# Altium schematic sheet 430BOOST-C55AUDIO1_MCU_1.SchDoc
size A4; PageSetup: Record=PageOptions|CenterHorizontal=True|CenterVertical=True|PrintScale=1.00|XCorrection=1.00|YCorrection=1.00|PrintKind=0|BorderSize=5000000|LeftOffset=0|BottomOffset=0|Orientation=2|PaperLength=1000|PaperWidth=1000|Scale=100|PaperSource=7|PrintQuality=-4|MediaType=1|DitherType=10|PaperKind=A4|PrintScaleMode=1
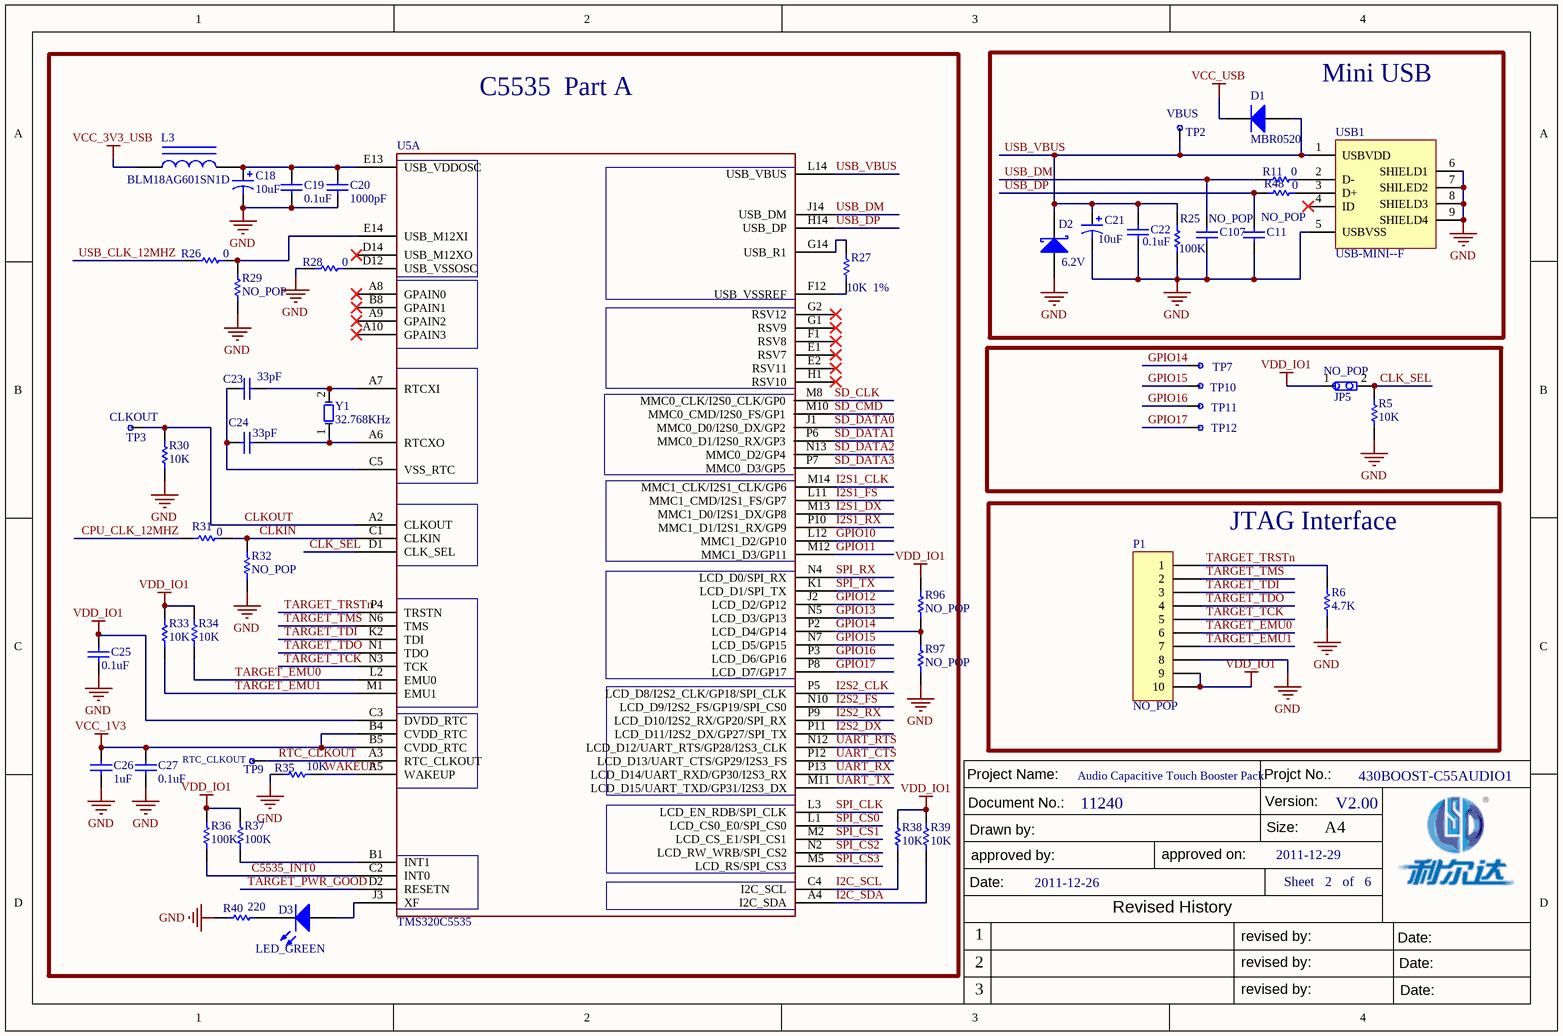
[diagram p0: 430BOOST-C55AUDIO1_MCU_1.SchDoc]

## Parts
C11  NO_POP  [0402-C]
C18  10uF  [0805-C]
C19  0.1uF  [0402-C]
C20  1000pF  [0402-C]
C21  10uF  [0805-C]
C22  0.1uF  [0402-C]
C23  33pF  [0402-C]
C24  33pF  [0402-C]
C25  0.1uF  [0402-C]
C26  1uF  [0603-C]
C27  0.1uF  [0402-C]
C107  NO_POP  [0402-C]
D1  MBR0520  [SOD-123-1]
D2  6.2V  [SOD-123-1]
D3  LED_GREEN  [0603-1]
JP5  NO_POP  [SIP2-2.54]
L3  BLM18AG601SN1D  [0603-L]
P1  NO_POP  [SIP10-2.0]
R5  10K  [0402-R]
R6  4.7K  [0402-R]
R11  0  [0402-R]
R25  100K  [0402-R]
R26  0  [0402-R]
R27  10K  1%  [0402-R]
R28  0  [0402-R]
R29  NO_POP  [0402-R]
R30  10K  [0402-R]
R31  0  [0402-R]
R32  NO_POP  [0402-R]
R33  10K  [0402-R]
R34  10K  [0402-R]
R35  10K  [0402-R]
R36  100K  [0402-R]
R37  100K  [0402-R]
R38  10K  [0402-R]
R39  10K  [0402-R]
R40  220  [0402-R]
R48  0  [0402-R]
R96  NO_POP  [0402-R]
R97  NO_POP  [0402-R]
TP2  VBUS  [SIP1-TEST]
TP3  CLKOUT  [SIP1-TEST]
TP7  TextPoint  [SIP1-TEST]  (value not drawn)
TP9  RTC_CLKOUT  [SIP1-TEST]
TP10  TextPoint  [SIP1-TEST]  (value not drawn)
TP11  TextPoint  [SIP1-TEST]  (value not drawn)
TP12  TextPoint  [SIP1-TEST]  (value not drawn)
U5  TMS320C5535  [BGA-N144-0.8MM]  (part A of 2)
USB1  USB-MINI--F  [USB-MIN-F]
Y1  32.768KHz  [SMD4015-2]

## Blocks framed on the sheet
C5535  Part A: C18-C20 C23-C27 D3 L3 R26-R40 R96 R97 TP3 TP9 U5 Y1
Mini USB: C11 C21 C22 C107 D1 D2 R11 R25 R48 TP2 USB1
JTAG Interface: P1 R6

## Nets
GND: C11.2 C18.2 C19.1 C20.1 C21.2 C22.2 C25.1 C26.1 C27.1 C107.2 D2.1(A) P1.8 R5.1 R6.1 R25.1 R28.1 R29.1 R30.1 R32.1 R35.1 R40.1 R97.2 USB1.5(USBVSS) USB1.6(SHIELD1) USB1.7(SHILED2) USB1.8(SHIELD3) USB1.9(SHIELD4)
VCC_1V3: C26.2 C27.2 U5.B4(CVDD_RTC) U5.B5(CVDD_RTC)
VCC_3V3_USB: L3.1
VCC_USB: D1.2(K)
VDD_IO1: C25.2 JP5.1 P1.9 P1.10 R33.2 R34.2 R36.2 R37.2 R38.2 R39.2 R96.2 U5.C3(DVDD_RTC)
C5535_INT0: R36.1 U5.C2(INT0)
CLK_SEL: JP5.2 R5.2 U5.D1(CLK_SEL)
CLKIN: R31.1 R32.2 U5.C1(CLKIN)
CLKOUT: R30.2 TP3.1 U5.A2(CLKOUT)
CPU_CLK_12MHZ: R31.2
GPIO10: U5.L12(MMC1_D2/GP10)
GPIO11: U5.M12(MMC1_D3/GP11)
GPIO12: U5.J2(LCD_D2/GP12)
GPIO13: U5.N5(LCD_D3/GP13)
GPIO14: R96.1 R97.1 TP7.1 U5.P2(LCD_D4/GP14)
GPIO15: TP10.1 U5.N7(LCD_D5/GP15)
GPIO16: TP11.1 U5.P3(LCD_D6/GP16)
GPIO17: TP12.1 U5.P8(LCD_D7/GP17)
I2C_SCL: R38.1 U5.C4(I2C_SCL)
I2C_SDA: R39.1 U5.A4(I2C_SDA)
I2S1_CLK: U5.M14(MMC1_CLK/I2S1_CLK/GP6)
I2S1_DX: U5.M13(MMC1_D0/I2S1_DX/GP8)
I2S1_FS: U5.L11(MMC1_CMD/I2S1_FS/GP7)
I2S1_RX: U5.P10(MMC1_D1/I2S1_RX/GP9)
I2S2_CLK: U5.P5(LCD_D8/I2S2_CLK/GP18/SPI_CLK)
I2S2_DX: U5.P11(LCD_D11/I2S2_DX/GP27/SPI_TX)
I2S2_FS: U5.N10(LCD_D9/I2S2_FS/GP19/SPI_CS0)
I2S2_RX: U5.P9(LCD_D10/I2S2_RX/GP20/SPI_RX)
RTC_CLKOUT: TP9.1 U5.A3(RTC_CLKOUT)
SD_CLK: U5.M8(MMC0_CLK/I2S0_CLK/GP0)
SD_CMD: U5.M10(MMC0_CMD/I2S0_FS/GP1)
SD_DATA0: U5.J1(MMC0_D0/I2S0_DX/GP2)
SD_DATA1: U5.P6(MMC0_D1/I2S0_RX/GP3)
SD_DATA2: U5.N13(MMC0_D2/GP4)
SD_DATA3: U5.P7(MMC0_D3/GP5)
SPI_CLK: U5.L3(LCD_EN_RDB/SPI_CLK)
SPI_CS0: U5.L1(LCD_CS0_E0/SPI_CS0)
SPI_CS1: U5.M2(LCD_CS_E1/SPI_CS1)
SPI_CS2: U5.N2(LCD_RW_WRB/SPI_CS2)
SPI_CS3: U5.M5(LCD_RS/SPI_CS3)
SPI_RX: U5.N4(LCD_D0/SPI_RX)
SPI_TX: U5.K1(LCD_D1/SPI_TX)
TARGET_EMU0: P1.6 R34.1 U5.L2(EMU0)
TARGET_EMU1: P1.7 R33.1 U5.M1(EMU1)
TARGET_PWR_GOOD: U5.D2(RESETN)
TARGET_TCK: P1.5 U5.N3(TCK)
TARGET_TDI: P1.3 U5.K2(TDI)
TARGET_TDO: P1.4 U5.N1(TDO)
TARGET_TMS: P1.2 U5.N6(TMS)
TARGET_TRSTn: P1.1 R6.2 U5.P4(TRSTN)
UART_CTS: U5.P12(LCD_D13/UART_CTS/GP29/I2S3_FS)
UART_RTS: U5.N12(LCD_D12/UART_RTS/GP28/I2S3_CLK)
UART_RX: U5.P13(LCD_D14/UART_RXD/GP30/I2S3_RX)
UART_TX: U5.M11(LCD_D15/UART_TXD/GP31/I2S3_DX)
USB_CLK_12MHZ: R26.1
USB_DM: C107.1 R11.1 U5.J14(USB_DM)
USB_DP: C11.1 R48.1 U5.H14(USB_DP)
USB_VBUS: C21.1 C22.1 D1.1(A) D2.2(K) R25.2 TP2.1 U5.L14(USB_VBUS) USB1.1(USBVDD)
WAKEUP: R35.2 U5.A5(WAKEUP)
NetC18_1: C18.1 C19.2 C20.2 L3.2 U5.E13(USB_VDDOSC)
NetC23_1: C23.1 C24.1 U5.C5(VSS_RTC)
NetC23_2: C23.2 U5.A7(RTCXI) Y1.2
NetC24_2: C24.2 U5.A6(RTCXO) Y1.1
NetD3_1: D3.1(A) U5.J3(XF)
NetD3_2: D3.2(K) R40.2
NetR11_2: R11.2 USB1.2(D-)
NetR26_2: R26.2 R29.2 U5.E14(USB_M12XI)
NetR27_1: R27.1 U5.F12(USB_VSSREF)
NetR27_2: R27.2 U5.G14(USB_R1)
NetR28_2: R28.2 U5.D12(USB_VSSOSC)
NetR37_1: R37.1 U5.B1(INT1)
NetR48_2: R48.2 USB1.3(D+)

Not connected (* = marked no-connect by the designer): U5 A8(GPAIN0)* A9(GPAIN2)* A10(GPAIN3)* B8(GPAIN1)* D14(USB_M12XO)* E1(RSV7)* E2(RSV11)* F1(RSV8)* G1(RSV9)* G2(RSV12)* H1(RSV10)*; USB1 4(ID)*

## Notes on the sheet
- Audio Capacitive Touch Booster Pack
- 430BOOST-C55AUDIO1
- 11240
- V2.00
- 2011-12-26
- 2011-12-29
- Sheet   2   of   6

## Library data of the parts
C11 C19 C20 C22-C27 C107 = Cap: Capacitor; Value: 100pF
C18 C21 = Cap Pol1: Polarized Capacitor (Radial); Value: 100pF
D1 = Diode: Default Diode
D2 = Diode 10TQ045: Schottky Rectifier; Note: Terminal 2 is the TAB and is electrically connected to the cathode
D3 = LED0: Typical INFRARED GaAs LED
JP5 = JUMPER
L3 = Inductor Iron: Magnetic-Core Inductor; Value: 10mH
P1 = Header 10: Header, 10-Pin
R5 R6 R11 R25-R40 R48 R96 R97 = Res1: Resistor; Value: 1K
TP2 TP3 TP9 = TextPoint
Y1 = XTAL-4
